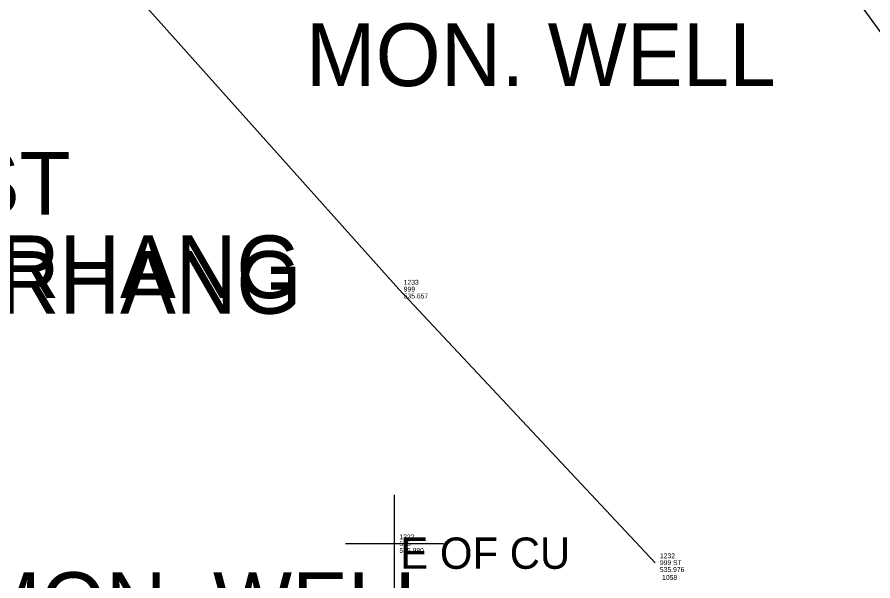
# Model space of a CAD drawing. Extents: x 5447 to 709667, y 4528 to 375505.
# Drawn here: x 706317.34 to 706361.06, y 375006.58 to 375035.4 of the extents above; entities that cross this region are included whole.
import ezdxf

# ---------------------------------------------------------------- set-up
doc = ezdxf.new("R2010")
doc.units = 0
for name, color, linetype in [('SV_BKLN_BKLN', 7, 'Continuous'), ('SV_NODES_ACTIVE_POINT', 7, 'Continuous'), ('SV_NODES_DESCRIPTION', 7, 'Continuous'), ('SV_NODES_ELEVATION', 7, 'Continuous'), ('SV_NODES_PT_NUMBER', 7, 'Continuous'), ('SV_SIGN_SIGN_TX', 7, 'Continuous'), ('SV_SURF_SPOT', 7, 'Continuous'), ('SV_SURVEY_NOTES', 7, 'Continuous'), ('SV_WATR_WATER_TX', 7, 'Continuous')]:
    doc.layers.add(name, color=color, linetype=linetype)

msp = doc.modelspace()

# ---------------------------------------------------------------- linework, layer by layer
at = {"layer": 'SV_BKLN_BKLN'}
for points in [[(706347.672, 375053.865), (706359.079, 375037.88), (706372.203, 375019.867)], [(706349.934, 375007.515), (706336.844, 375021.495), (706322.096, 375038.007)]]:
    msp.add_lwpolyline(points, dxfattribs=at)
at = {"layer": 'SV_NODES_ACTIVE_POINT'}
for p, q in [((706336.844, 375021.495), (706336.844, 375021.495)), ((706349.934, 375007.515), (706349.934, 375007.515))]:
    msp.add_line(p, q, dxfattribs=at)
at = {"layer": 'SV_SURF_SPOT'}
for p, q in [((706336.624, 375005.988), (706336.624, 375010.99)), ((706334.123, 375008.489), (706339.125, 375008.489)), ((706336.624, 375008.489), (706336.624, 375008.489))]:
    msp.add_line(p, q, dxfattribs=at)

# ---------------------------------------------------------------- texts
at = {"layer": 'SV_NODES_DESCRIPTION'}
for s, p in [('999', (706337.094, 375021.37)), ('515', (706336.874, 375008.364)), ('999 ST', (706350.184, 375007.39))]:
    msp.add_text(s, height=0.25, dxfattribs=at).set_placement(p)
at = {"layer": 'SV_NODES_ELEVATION'}
for s, p in [('535.657', (706337.094, 375021.02)), ('535.980', (706336.874, 375008.014)), ('535.976', (706350.184, 375007.04))]:
    msp.add_text(s, height=0.25, dxfattribs=at).set_placement(p)
at = {"layer": 'SV_NODES_PT_NUMBER'}
for s, p in [('1233', (706337.094, 375021.72)), ('1222', (706336.874, 375008.714)), ('1232', (706350.184, 375007.74)), ('1058', (706350.296, 375006.634))]:
    msp.add_text(s, height=0.25, dxfattribs=at).set_placement(p)
at = {"layer": 'SV_SIGN_SIGN_TX'}
msp.add_text('MTL. POST', height=3.2, dxfattribs=at).set_placement((706297.494, 375025.305))
at = {"layer": 'SV_SURVEY_NOTES'}
for s, height, p in [('OVRHANG', 3.2, (706310.236, 375021.037)), ('OVRHANG', 3.2, (706310.236, 375021.037)), ('OVRHANG', 3.2, (706310.236, 375021.037)), ('OVRHANG', 3.2, (706310.236, 375021.037)), ('OVRHANG', 3.2, (706310.236, 375021.037)), ('OVRHANG', 3.2, (706310.236, 375021.037)), ('OVRHANG', 3.2, (706310.236, 375021.037)), ('OVRHANG', 3.2, (706310.236, 375021.037)), ('OVRHANG', 3.2, (706310.236, 375020.237)), ('OVRHANG', 3.2, (706310.236, 375020.237)), ('OVRHANG', 3.2, (706310.236, 375020.237)), ('E OF CU', 1.6, (706336.922, 375007.202))]:
    msp.add_text(s, height=height, dxfattribs=at).set_placement(p)
at = {"layer": 'SV_WATR_WATER_TX'}
for p in [(706332.091, 375031.872), (706314.988, 375003.827)]:
    msp.add_text('MON. WELL', height=3.2, dxfattribs=at).set_placement(p)

doc.saveas('drawing.dxf')
